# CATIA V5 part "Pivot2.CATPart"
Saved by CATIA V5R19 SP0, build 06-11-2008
Part number: Pivot2
Bounding box of the stored display mesh (mm): x 10.315 to 19.685, y 7.3 to 16.7, z 2.5 to 17.5
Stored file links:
  F:\IAO\Catia\Pivot2.CATPart
  F:\IAO\Catia\Etau.CATProduct
  F:\IAO\Catia\Squelette_pivot2.CATPart
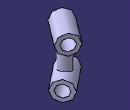
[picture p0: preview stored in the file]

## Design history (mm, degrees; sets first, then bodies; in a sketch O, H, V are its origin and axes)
Set1
  Plane1: linked copy from another document
  Point1: linked copy from another document
  Plane2: linked copy from another document
  Point2: linked copy from another document
Body1 (main body)
  Sketch1 on Plane1, origin (15, 12, 0), H (-0.6247, 0.7809, 0), V (0, 0, 1)
    circle A1 centre (0, 5) radius 1.5
    point P1 (0, 5)
    reference projected point E1 (0, 5) from Point1
    circle A2 centre (0, 5) radius 2.5
    radius A1 = 1.5
    radius A2 = 2.5
    coincidence: P1 E1
  Pad1: profile Sketch1, direction (0.7809, 0.6247, 0), length 4, mirrored extent
  Sketch2 on Plane2, origin (11.16, 14.88, 0), H (-0.8, 0.6, 0), V (0, 0, 1)
    circle A1 centre (-4.8, 15) radius 1.5
    point P1 (-4.8, 15)
    circle A2 centre (-4.8, 15) radius 2.5
    reference projected point E1 (-4.8, 15) from Point2
    radius A1 = 1.5
    radius A2 = 2.5
    coincidence: P1 E1
  Pad2: profile Sketch2, direction (0.6, 0.8, 0), length 4, mirrored extent
  Sketch3 on Plane2, origin (11.16, 14.88, 0), H (-0.8, 0.6, 0), V (0, 0, 1)
    line L1 (-4.8, 13.3) -> (-3.3, 13.3)
    line L2 (-3.3, 13.3) -> (-3.3, 7.1)
    line L3 (-3.3, 7.1) -> (-4.8, 7.1)
    line L4 (-4.8, 7.1) -> (-4.8, 13.3)
    reference projected point E1 (-4.8, 15) from Point2
    reference projected point E2 (-4.8, 15) from Point2
    length L4 = 6.2
    distance L1 E2 = 1.7
    length L1 = 1.5
    horizontal: L1 H, L3 H
    vertical: L2 V, L4 V
    coincidence: L4 E1
  Shaft1: profile Sketch3, axis Sketch3.L4, angle 360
